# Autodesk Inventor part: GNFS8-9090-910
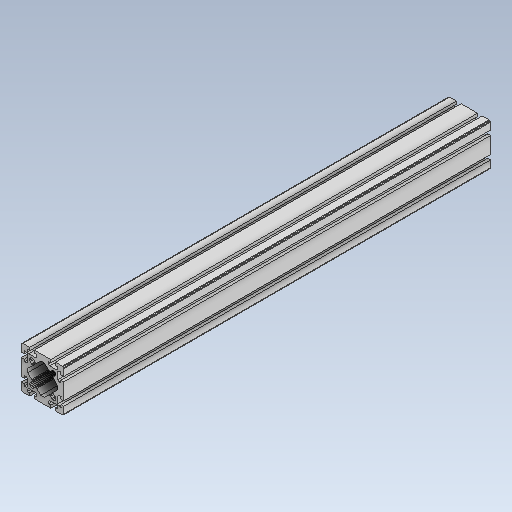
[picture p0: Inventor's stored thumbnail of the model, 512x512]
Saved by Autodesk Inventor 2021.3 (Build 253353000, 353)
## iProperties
Created: 2022-02
Part Number: GNFS8-9090-910
Material: 一般
Document SubType Name: Modeling
Designer: kengo
Density: 1 g/cm^3
Appearance: 既定
Author: kengo
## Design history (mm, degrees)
feature "GNFS8-9090-910"
node "ソリッド1"
